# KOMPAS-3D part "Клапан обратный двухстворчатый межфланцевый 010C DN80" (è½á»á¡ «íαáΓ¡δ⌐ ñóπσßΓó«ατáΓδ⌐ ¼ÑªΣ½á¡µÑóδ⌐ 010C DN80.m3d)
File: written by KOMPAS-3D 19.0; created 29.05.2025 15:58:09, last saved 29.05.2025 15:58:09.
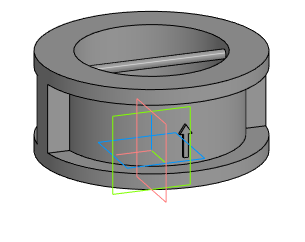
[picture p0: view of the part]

Document properties: Полное имя файла: E:\Dendor Работа Сачек\3D для проекитирвщиков\5.2 Тип 010C, 010C.Y Клапан обратный двухстворчатый межфланцевый\stp_Клапан обратный двухстворчатый межфланцевый 010C\Клапан обратный двухстворчатый межфланцевый 010C DN80.m3d

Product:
- Part/product: Клапан обратный двухстворчатый межфланцевый 010C DN80

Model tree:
1. Операция без истории:1  (labels: Клапан обратный двухстворчатый межфланцевый 010C DN80)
